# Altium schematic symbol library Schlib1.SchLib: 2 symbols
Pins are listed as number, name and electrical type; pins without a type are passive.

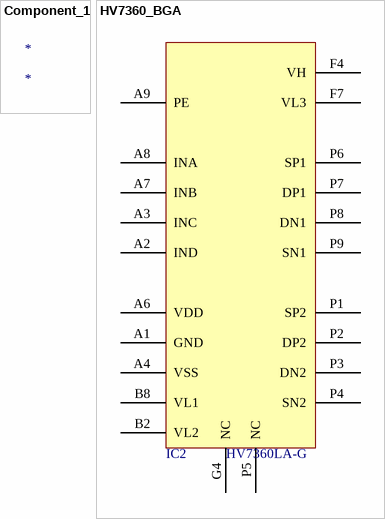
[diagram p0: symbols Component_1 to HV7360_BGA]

## Component_1
designator *

## HV7360_BGA
designator IC2, comment HV7360LA-G
Part Description: High Speed, ±100V 2.5A Two or Three Level Ultrasound Pulser; Manufacturer: Supertex inc.; Table: Analog & Interface
footprint HV7360_BGA
pins: A1 GND, A2 IND, A3 INC, A4 VSS, A6 VDD, A7 INB, A8 INA, A9 PE, B2 VL2, B8 VL1, F4 VH, F7 VL3, G4 NC, P1 SP2, P2 DP2, P3 DN2, P4 SN2, P5 NC, P6 SP1, P7 DP1, P8 DN1, P9 SN1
